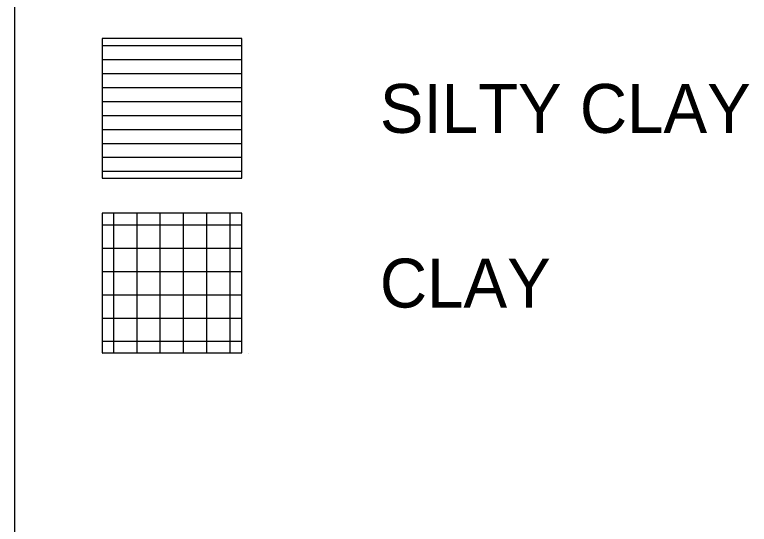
# Model space of a CAD drawing. Extents: x -59 to 43, y 0 to 22.
# Drawn here: x 11.667 to 13.769, y 16.524 to 17.983 of the extents above; entities that cross this region are included whole.
import ezdxf

# ---------------------------------------------------------------- set-up
doc = ezdxf.new("R2010")
doc.units = 0
for name, color, linetype in [('Default', 7, 'Continuous'), ('SH_Data', 7, 'Continuous'), ('SH_Text', 7, 'Continuous')]:
    doc.layers.add(name, color=color, linetype=linetype)

msp = doc.modelspace()

# ---------------------------------------------------------------- linework, layer by layer
at = {"layer": 'Default'}
for p, q in [((11.9167, 17.915), (11.9167, 17.915)), ((12.3167, 17.915), (12.3167, 17.915)), ((11.9167, 17.895), (12.3167, 17.895)), ((11.9167, 17.855), (12.3167, 17.855)), ((11.9167, 17.815), (12.3167, 17.815)), ((11.9167, 17.775), (12.3167, 17.775)), ((11.9167, 17.735), (12.3167, 17.735)), ((11.9167, 17.695), (12.3167, 17.695)), ((11.9167, 17.655), (12.3167, 17.655)), ((11.9167, 17.615), (12.3167, 17.615)), ((11.9167, 17.575), (12.3167, 17.575)), ((11.9167, 17.535), (12.3167, 17.535)), ((11.9167, 17.515), (11.9167, 17.515)), ((12.3167, 17.515), (12.3167, 17.515)), ((11.9167, 17.0128), (11.9167, 17.0128)), ((12.3345, 17.0128), (12.3345, 17.0128))]:
    msp.add_line(p, q, dxfattribs=at)
at = {"layer": 'SH_Data'}
msp.add_line((11.6667, 5.18), (11.6667, 21), dxfattribs=at)
for points in [[(11.9167, 17.515), (12.3167, 17.515), (12.3167, 17.915), (11.9167, 17.915)], [(11.9167, 17.015), (12.3167, 17.015), (12.3167, 17.415), (11.9167, 17.415)]]:
    msp.add_lwpolyline(points, close=True, dxfattribs=at)
at = {"layer": 'SH_Text'}
for p, q in [((11.9167, 17.415), (11.9167, 17.415)), ((11.95, 17.015), (11.95, 17.415)), ((12.0167, 17.015), (12.0167, 17.415)), ((12.0834, 17.015), (12.0834, 17.415)), ((12.15, 17.015), (12.15, 17.415)), ((12.2167, 17.015), (12.2167, 17.415)), ((12.2834, 17.015), (12.2834, 17.415)), ((12.3167, 17.415), (12.3167, 17.415)), ((11.9167, 17.3816), (12.3167, 17.3816)), ((11.9167, 17.315), (12.3167, 17.315)), ((11.9167, 17.2483), (12.3167, 17.2483)), ((11.9167, 17.1816), (12.3167, 17.1816)), ((11.9167, 17.115), (12.3167, 17.115)), ((11.9167, 17.0483), (12.3167, 17.0483)), ((11.9167, 17.015), (11.9167, 17.015)), ((12.3167, 17.015), (12.3167, 17.015))]:
    msp.add_line(p, q, dxfattribs=at)

# ---------------------------------------------------------------- texts
for s, p in [('SILTY CLAY', (12.7116, 17.645)), ('CLAY', (12.7116, 17.145))]:
    msp.add_text(s, height=0.14, dxfattribs=at).set_placement(p)

doc.saveas('drawing.dxf')
